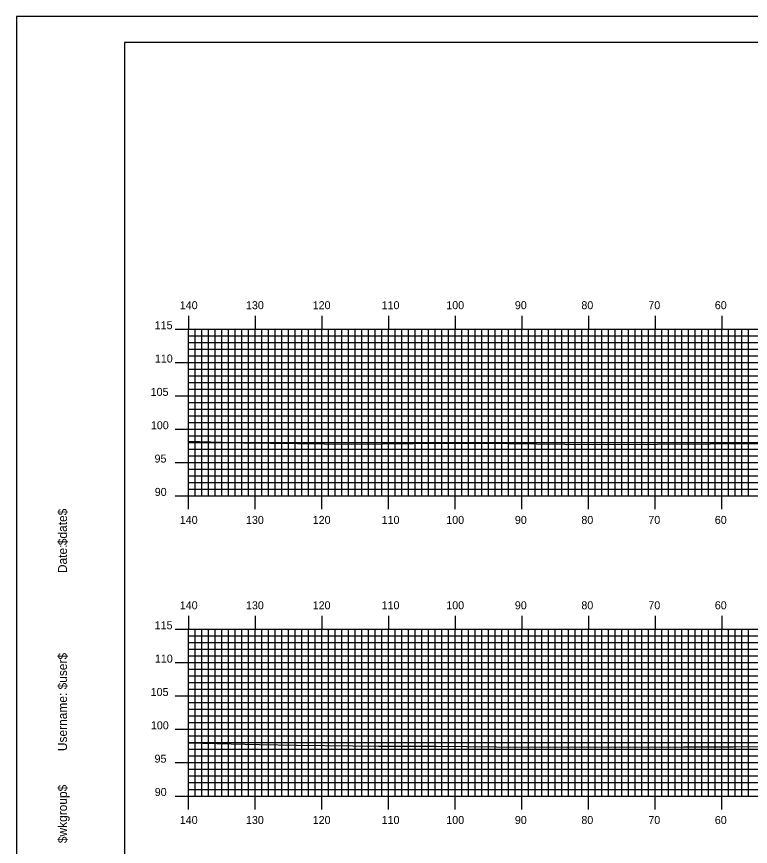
# Model space of a CAD drawing. Extents: x 1764939 to 1765282, y 442591 to 442811.
# Drawn here: x 1764939.1 to 1765049.2, y 442686.1 to 442810.5 of the extents above; entities that cross this region are included whole.
import ezdxf

# ---------------------------------------------------------------- set-up
doc = ezdxf.new("R2010")
doc.units = 0
for name, color, linetype in [('BORDER', 7, 'Continuous'), ('H_V ANNOTATION', 7, 'Continuous'), ('MAJOR', 7, 'Continuous'), ('MINOR', 7, 'Continuous'), ('PLOT BOUNDARY', 7, 'Continuous'), ('S_Roadway_Centerline', 7, 'Continuous')]:
    doc.layers.add(name, color=color, linetype=linetype)

msp = doc.modelspace()

# ---------------------------------------------------------------- linework, layer by layer
at = {"layer": 'BORDER'}
msp.add_lwpolyline([(1764955.26, 442596.67), (1765275.26, 442596.67), (1765275.26, 442806.67), (1764955.26, 442806.67)], close=True, dxfattribs=at)
at = {"layer": 'MAJOR'}
for p, q in [((1764964.86, 442765.67), (1764964.86, 442763.67)), ((1764974.86, 442765.67), (1764974.86, 442763.67)), ((1764984.86, 442765.67), (1764984.86, 442763.67)), ((1764994.86, 442765.67), (1764994.86, 442763.67)), ((1765004.86, 442765.67), (1765004.86, 442763.67)), ((1765014.86, 442765.67), (1765014.86, 442763.67)), ((1765024.86, 442765.67), (1765024.86, 442763.67)), ((1765034.86, 442765.67), (1765034.86, 442763.67)), ((1765044.86, 442765.67), (1765044.86, 442763.67)), ((1764962.85, 442763.67), (1764964.86, 442763.67)), ((1764964.86, 442763.67), (1765244.86, 442763.67)), ((1764964.86, 442738.67), (1764964.86, 442763.67)), ((1764964.86, 442738.67), (1764964.86, 442763.67)), ((1764964.86, 442763.67), (1765244.86, 442763.67)), ((1764974.86, 442738.67), (1764974.86, 442763.67)), ((1764984.86, 442738.67), (1764984.86, 442763.67)), ((1764994.86, 442738.67), (1764994.86, 442763.67)), ((1765004.86, 442738.67), (1765004.86, 442763.67)), ((1765014.86, 442738.67), (1765014.86, 442763.67)), ((1765024.86, 442738.67), (1765024.86, 442763.67)), ((1765034.86, 442738.67), (1765034.86, 442763.67)), ((1765044.86, 442738.67), (1765044.86, 442763.67)), ((1764962.85, 442758.67), (1764964.86, 442758.67)), ((1764964.86, 442758.67), (1765244.86, 442758.67)), ((1764962.85, 442753.67), (1764964.86, 442753.67)), ((1764964.86, 442753.67), (1765244.86, 442753.67)), ((1764962.85, 442748.67), (1764964.86, 442748.67)), ((1764964.86, 442748.67), (1765244.86, 442748.67)), ((1764962.85, 442743.67), (1764964.86, 442743.67)), ((1764964.86, 442743.67), (1765244.86, 442743.67)), ((1764962.85, 442738.67), (1764964.86, 442738.67)), ((1764964.86, 442738.67), (1765244.86, 442738.67)), ((1764964.86, 442738.67), (1765244.86, 442738.67)), ((1764964.86, 442736.66), (1764964.86, 442738.67)), ((1764974.86, 442736.66), (1764974.86, 442738.67)), ((1764984.86, 442736.66), (1764984.86, 442738.67)), ((1764994.86, 442736.66), (1764994.86, 442738.67)), ((1765004.86, 442736.66), (1765004.86, 442738.67)), ((1765014.86, 442736.66), (1765014.86, 442738.67)), ((1765024.86, 442736.66), (1765024.86, 442738.67)), ((1765034.86, 442736.66), (1765034.86, 442738.67)), ((1765044.86, 442736.66), (1765044.86, 442738.67)), ((1764964.86, 442720.67), (1764964.86, 442718.67)), ((1764974.86, 442720.67), (1764974.86, 442718.67)), ((1764984.86, 442720.67), (1764984.86, 442718.67)), ((1764994.86, 442720.67), (1764994.86, 442718.67)), ((1765004.86, 442720.67), (1765004.86, 442718.67)), ((1765014.86, 442720.67), (1765014.86, 442718.67)), ((1765024.86, 442720.67), (1765024.86, 442718.67)), ((1765034.86, 442720.67), (1765034.86, 442718.67)), ((1765044.86, 442720.67), (1765044.86, 442718.67)), ((1764962.85, 442718.67), (1764964.86, 442718.67)), ((1764964.86, 442718.67), (1765244.86, 442718.67)), ((1764964.86, 442693.67), (1764964.86, 442718.67)), ((1764964.86, 442693.67), (1764964.86, 442718.67)), ((1764964.86, 442718.67), (1765244.86, 442718.67)), ((1764974.86, 442693.67), (1764974.86, 442718.67)), ((1764984.86, 442693.67), (1764984.86, 442718.67)), ((1764994.86, 442693.67), (1764994.86, 442718.67)), ((1765004.86, 442693.67), (1765004.86, 442718.67)), ((1765014.86, 442693.67), (1765014.86, 442718.67)), ((1765024.86, 442693.67), (1765024.86, 442718.67)), ((1765034.86, 442693.67), (1765034.86, 442718.67)), ((1765044.86, 442693.67), (1765044.86, 442718.67)), ((1764962.85, 442713.67), (1764964.86, 442713.67)), ((1764964.86, 442713.67), (1765244.86, 442713.67)), ((1764962.85, 442708.67), (1764964.86, 442708.67)), ((1764964.86, 442708.67), (1765244.86, 442708.67)), ((1764962.85, 442703.67), (1764964.86, 442703.67)), ((1764964.86, 442703.67), (1765244.86, 442703.67)), ((1764962.85, 442698.67), (1764964.86, 442698.67)), ((1764964.86, 442698.67), (1765244.86, 442698.67)), ((1764962.85, 442693.67), (1764964.86, 442693.67)), ((1764964.86, 442693.67), (1765244.86, 442693.67)), ((1764964.86, 442693.67), (1765244.86, 442693.67)), ((1764964.86, 442691.66), (1764964.86, 442693.67)), ((1764974.86, 442691.66), (1764974.86, 442693.67)), ((1764984.86, 442691.66), (1764984.86, 442693.67)), ((1764994.86, 442691.66), (1764994.86, 442693.67)), ((1765004.86, 442691.66), (1765004.86, 442693.67)), ((1765014.86, 442691.66), (1765014.86, 442693.67)), ((1765024.86, 442691.66), (1765024.86, 442693.67)), ((1765034.86, 442691.66), (1765034.86, 442693.67)), ((1765044.86, 442691.66), (1765044.86, 442693.67))]:
    msp.add_line(p, q, dxfattribs=at)
at = {"layer": 'MINOR'}
for p, q in [((1764964.86, 442762.67), (1765244.86, 442762.67)), ((1764964.86, 442762.67), (1764966.86, 442762.67)), ((1764965.86, 442738.67), (1764965.86, 442763.67)), ((1764966.86, 442738.67), (1764966.86, 442763.67)), ((1764967.86, 442738.67), (1764967.86, 442763.67)), ((1764968.86, 442738.67), (1764968.86, 442763.67)), ((1764969.86, 442738.67), (1764969.86, 442763.67)), ((1764970.86, 442738.67), (1764970.86, 442763.67)), ((1764971.86, 442738.67), (1764971.86, 442763.67)), ((1764972.86, 442738.67), (1764972.86, 442763.67)), ((1764973.86, 442738.67), (1764973.86, 442763.67)), ((1764975.86, 442738.67), (1764975.86, 442763.67)), ((1764976.86, 442738.67), (1764976.86, 442763.67)), ((1764977.86, 442738.67), (1764977.86, 442763.67)), ((1764978.86, 442738.67), (1764978.86, 442763.67)), ((1764979.86, 442738.67), (1764979.86, 442763.67)), ((1764980.86, 442738.67), (1764980.86, 442763.67)), ((1764981.86, 442738.67), (1764981.86, 442763.67)), ((1764982.86, 442738.67), (1764982.86, 442763.67)), ((1764983.86, 442738.67), (1764983.86, 442763.67)), ((1764985.86, 442738.67), (1764985.86, 442763.67)), ((1764986.86, 442738.67), (1764986.86, 442763.67)), ((1764987.86, 442738.67), (1764987.86, 442763.67)), ((1764988.86, 442738.67), (1764988.86, 442763.67)), ((1764989.86, 442738.67), (1764989.86, 442763.67)), ((1764990.86, 442738.67), (1764990.86, 442763.67)), ((1764991.86, 442738.67), (1764991.86, 442763.67)), ((1764992.86, 442738.67), (1764992.86, 442763.67)), ((1764993.86, 442738.67), (1764993.86, 442763.67)), ((1764995.86, 442738.67), (1764995.86, 442763.67)), ((1764996.86, 442738.67), (1764996.86, 442763.67)), ((1764997.86, 442738.67), (1764997.86, 442763.67)), ((1764998.86, 442738.67), (1764998.86, 442763.67)), ((1764999.86, 442738.67), (1764999.86, 442763.67)), ((1765000.86, 442738.67), (1765000.86, 442763.67)), ((1765001.86, 442738.67), (1765001.86, 442763.67)), ((1765002.86, 442738.67), (1765002.86, 442763.67)), ((1765003.86, 442738.67), (1765003.86, 442763.67)), ((1765005.86, 442738.67), (1765005.86, 442763.67)), ((1765006.86, 442738.67), (1765006.86, 442763.67)), ((1765007.86, 442738.67), (1765007.86, 442763.67)), ((1765008.86, 442738.67), (1765008.86, 442763.67)), ((1765009.86, 442738.67), (1765009.86, 442763.67)), ((1765010.86, 442738.67), (1765010.86, 442763.67)), ((1765011.86, 442738.67), (1765011.86, 442763.67)), ((1765012.86, 442738.67), (1765012.86, 442763.67)), ((1765013.86, 442738.67), (1765013.86, 442763.67)), ((1765015.86, 442738.67), (1765015.86, 442763.67)), ((1765016.86, 442738.67), (1765016.86, 442763.67)), ((1765017.86, 442738.67), (1765017.86, 442763.67)), ((1765018.86, 442738.67), (1765018.86, 442763.67)), ((1765019.86, 442738.67), (1765019.86, 442763.67)), ((1765020.86, 442738.67), (1765020.86, 442763.67)), ((1765021.86, 442738.67), (1765021.86, 442763.67)), ((1765022.86, 442738.67), (1765022.86, 442763.67)), ((1765023.86, 442738.67), (1765023.86, 442763.67)), ((1765025.86, 442738.67), (1765025.86, 442763.67)), ((1765026.86, 442738.67), (1765026.86, 442763.67)), ((1765027.86, 442738.67), (1765027.86, 442763.67)), ((1765028.86, 442738.67), (1765028.86, 442763.67)), ((1765029.86, 442738.67), (1765029.86, 442763.67)), ((1765030.86, 442738.67), (1765030.86, 442763.67)), ((1765031.86, 442738.67), (1765031.86, 442763.67)), ((1765032.86, 442738.67), (1765032.86, 442763.67)), ((1765033.86, 442738.67), (1765033.86, 442763.67)), ((1765035.86, 442738.67), (1765035.86, 442763.67)), ((1765036.86, 442738.67), (1765036.86, 442763.67)), ((1765037.86, 442738.67), (1765037.86, 442763.67)), ((1765038.86, 442738.67), (1765038.86, 442763.67)), ((1765039.86, 442738.67), (1765039.86, 442763.67)), ((1765040.86, 442738.67), (1765040.86, 442763.67)), ((1765041.86, 442738.67), (1765041.86, 442763.67)), ((1765042.86, 442738.67), (1765042.86, 442763.67)), ((1765043.86, 442738.67), (1765043.86, 442763.67)), ((1765045.86, 442738.67), (1765045.86, 442763.67)), ((1765046.86, 442738.67), (1765046.86, 442763.67)), ((1765047.86, 442738.67), (1765047.86, 442763.67)), ((1765048.86, 442738.67), (1765048.86, 442763.67)), ((1764964.86, 442761.67), (1765244.86, 442761.67)), ((1764964.86, 442761.67), (1764966.86, 442761.67)), ((1764964.86, 442760.67), (1765244.86, 442760.67)), ((1764964.86, 442760.67), (1764966.86, 442760.67)), ((1764964.86, 442759.67), (1765244.86, 442759.67)), ((1764964.86, 442759.67), (1764966.86, 442759.67)), ((1764964.86, 442757.67), (1765244.86, 442757.67)), ((1764964.86, 442757.67), (1764966.86, 442757.67)), ((1764964.86, 442756.67), (1765244.86, 442756.67)), ((1764964.86, 442756.67), (1764966.86, 442756.67)), ((1764964.86, 442755.67), (1765244.86, 442755.67)), ((1764964.86, 442755.67), (1764966.86, 442755.67)), ((1764964.86, 442754.67), (1765244.86, 442754.67)), ((1764964.86, 442754.67), (1764966.86, 442754.67)), ((1764964.86, 442752.67), (1765244.86, 442752.67)), ((1764964.86, 442752.67), (1764966.86, 442752.67)), ((1764964.86, 442751.67), (1765244.86, 442751.67)), ((1764964.86, 442751.67), (1764966.86, 442751.67)), ((1764964.86, 442750.67), (1765244.86, 442750.67)), ((1764964.86, 442750.67), (1764966.86, 442750.67)), ((1764964.86, 442749.67), (1765244.86, 442749.67)), ((1764964.86, 442749.67), (1764966.86, 442749.67)), ((1764964.86, 442747.67), (1765244.86, 442747.67)), ((1764964.86, 442747.67), (1764966.86, 442747.67)), ((1764964.86, 442746.67), (1765244.86, 442746.67)), ((1764964.86, 442746.67), (1764966.86, 442746.67)), ((1764964.86, 442745.67), (1765244.86, 442745.67)), ((1764964.86, 442745.67), (1764966.86, 442745.67)), ((1764964.86, 442744.67), (1765244.86, 442744.67)), ((1764964.86, 442744.67), (1764966.86, 442744.67)), ((1764964.86, 442742.67), (1765244.86, 442742.67)), ((1764964.86, 442742.67), (1764966.86, 442742.67)), ((1764964.86, 442741.67), (1765244.86, 442741.67)), ((1764964.86, 442741.67), (1764966.86, 442741.67)), ((1764964.86, 442740.67), (1765244.86, 442740.67)), ((1764964.86, 442740.67), (1764966.86, 442740.67)), ((1764964.86, 442739.67), (1765244.86, 442739.67)), ((1764964.86, 442739.67), (1764966.86, 442739.67)), ((1764965.86, 442693.67), (1764965.86, 442718.67)), ((1764966.86, 442693.67), (1764966.86, 442718.67)), ((1764967.86, 442693.67), (1764967.86, 442718.67)), ((1764968.86, 442693.67), (1764968.86, 442718.67)), ((1764969.86, 442693.67), (1764969.86, 442718.67)), ((1764970.86, 442693.67), (1764970.86, 442718.67)), ((1764971.86, 442693.67), (1764971.86, 442718.67)), ((1764972.86, 442693.67), (1764972.86, 442718.67)), ((1764973.86, 442693.67), (1764973.86, 442718.67)), ((1764975.86, 442693.67), (1764975.86, 442718.67)), ((1764976.86, 442693.67), (1764976.86, 442718.67)), ((1764977.86, 442693.67), (1764977.86, 442718.67)), ((1764978.86, 442693.67), (1764978.86, 442718.67)), ((1764979.86, 442693.67), (1764979.86, 442718.67)), ((1764980.86, 442693.67), (1764980.86, 442718.67)), ((1764981.86, 442693.67), (1764981.86, 442718.67)), ((1764982.86, 442693.67), (1764982.86, 442718.67)), ((1764983.86, 442693.67), (1764983.86, 442718.67)), ((1764985.86, 442693.67), (1764985.86, 442718.67)), ((1764986.86, 442693.67), (1764986.86, 442718.67)), ((1764987.86, 442693.67), (1764987.86, 442718.67)), ((1764988.86, 442693.67), (1764988.86, 442718.67)), ((1764989.86, 442693.67), (1764989.86, 442718.67)), ((1764990.86, 442693.67), (1764990.86, 442718.67)), ((1764991.86, 442693.67), (1764991.86, 442718.67)), ((1764992.86, 442693.67), (1764992.86, 442718.67)), ((1764993.86, 442693.67), (1764993.86, 442718.67)), ((1764995.86, 442693.67), (1764995.86, 442718.67)), ((1764996.86, 442693.67), (1764996.86, 442718.67)), ((1764997.86, 442693.67), (1764997.86, 442718.67)), ((1764998.86, 442693.67), (1764998.86, 442718.67)), ((1764999.86, 442693.67), (1764999.86, 442718.67)), ((1765000.86, 442693.67), (1765000.86, 442718.67)), ((1765001.86, 442693.67), (1765001.86, 442718.67)), ((1765002.86, 442693.67), (1765002.86, 442718.67)), ((1765003.86, 442693.67), (1765003.86, 442718.67)), ((1765005.86, 442693.67), (1765005.86, 442718.67)), ((1765006.86, 442693.67), (1765006.86, 442718.67)), ((1765007.86, 442693.67), (1765007.86, 442718.67)), ((1765008.86, 442693.67), (1765008.86, 442718.67)), ((1765009.86, 442693.67), (1765009.86, 442718.67)), ((1765010.86, 442693.67), (1765010.86, 442718.67)), ((1765011.86, 442693.67), (1765011.86, 442718.67)), ((1765012.86, 442693.67), (1765012.86, 442718.67)), ((1765013.86, 442693.67), (1765013.86, 442718.67)), ((1765015.86, 442693.67), (1765015.86, 442718.67)), ((1765016.86, 442693.67), (1765016.86, 442718.67)), ((1765017.86, 442693.67), (1765017.86, 442718.67)), ((1765018.86, 442693.67), (1765018.86, 442718.67)), ((1765019.86, 442693.67), (1765019.86, 442718.67)), ((1765020.86, 442693.67), (1765020.86, 442718.67)), ((1765021.86, 442693.67), (1765021.86, 442718.67)), ((1765022.86, 442693.67), (1765022.86, 442718.67)), ((1765023.86, 442693.67), (1765023.86, 442718.67)), ((1765025.86, 442693.67), (1765025.86, 442718.67)), ((1765026.86, 442693.67), (1765026.86, 442718.67)), ((1765027.86, 442693.67), (1765027.86, 442718.67)), ((1765028.86, 442693.67), (1765028.86, 442718.67)), ((1765029.86, 442693.67), (1765029.86, 442718.67)), ((1765030.86, 442693.67), (1765030.86, 442718.67)), ((1765031.86, 442693.67), (1765031.86, 442718.67)), ((1765032.86, 442693.67), (1765032.86, 442718.67)), ((1765033.86, 442693.67), (1765033.86, 442718.67)), ((1765035.86, 442693.67), (1765035.86, 442718.67)), ((1765036.86, 442693.67), (1765036.86, 442718.67)), ((1765037.86, 442693.67), (1765037.86, 442718.67)), ((1765038.86, 442693.67), (1765038.86, 442718.67)), ((1765039.86, 442693.67), (1765039.86, 442718.67)), ((1765040.86, 442693.67), (1765040.86, 442718.67)), ((1765041.86, 442693.67), (1765041.86, 442718.67)), ((1765042.86, 442693.67), (1765042.86, 442718.67)), ((1765043.86, 442693.67), (1765043.86, 442718.67)), ((1765045.86, 442693.67), (1765045.86, 442718.67)), ((1765046.86, 442693.67), (1765046.86, 442718.67)), ((1765047.86, 442693.67), (1765047.86, 442718.67)), ((1765048.86, 442693.67), (1765048.86, 442718.67)), ((1764964.86, 442717.67), (1765244.86, 442717.67)), ((1764964.86, 442717.67), (1764966.86, 442717.67)), ((1764964.86, 442716.67), (1765244.86, 442716.67)), ((1764964.86, 442716.67), (1764966.86, 442716.67)), ((1764964.86, 442715.67), (1765244.86, 442715.67)), ((1764964.86, 442715.67), (1764966.86, 442715.67)), ((1764964.86, 442714.67), (1765244.86, 442714.67)), ((1764964.86, 442714.67), (1764966.86, 442714.67)), ((1764964.86, 442712.67), (1765244.86, 442712.67)), ((1764964.86, 442712.67), (1764966.86, 442712.67)), ((1764964.86, 442711.67), (1765244.86, 442711.67)), ((1764964.86, 442711.67), (1764966.86, 442711.67)), ((1764964.86, 442710.67), (1765244.86, 442710.67)), ((1764964.86, 442710.67), (1764966.86, 442710.67)), ((1764964.86, 442709.67), (1765244.86, 442709.67)), ((1764964.86, 442709.67), (1764966.86, 442709.67)), ((1764964.86, 442707.67), (1765244.86, 442707.67)), ((1764964.86, 442707.67), (1764966.86, 442707.67)), ((1764964.86, 442706.67), (1765244.86, 442706.67)), ((1764964.86, 442706.67), (1764966.86, 442706.67)), ((1764964.86, 442705.67), (1765244.86, 442705.67)), ((1764964.86, 442705.67), (1764966.86, 442705.67)), ((1764964.86, 442704.67), (1765244.86, 442704.67)), ((1764964.86, 442704.67), (1764966.86, 442704.67)), ((1764964.86, 442702.67), (1765244.86, 442702.67)), ((1764964.86, 442702.67), (1764966.86, 442702.67)), ((1764964.86, 442701.67), (1765244.86, 442701.67)), ((1764964.86, 442701.67), (1764966.86, 442701.67)), ((1764964.86, 442700.67), (1765244.86, 442700.67)), ((1764964.86, 442700.67), (1764966.86, 442700.67)), ((1764964.86, 442699.67), (1765244.86, 442699.67)), ((1764964.86, 442699.67), (1764966.86, 442699.67)), ((1764964.86, 442697.67), (1765244.86, 442697.67)), ((1764964.86, 442697.67), (1764966.86, 442697.67)), ((1764964.86, 442696.67), (1765244.86, 442696.67)), ((1764964.86, 442696.67), (1764966.86, 442696.67)), ((1764964.86, 442695.67), (1765244.86, 442695.67)), ((1764964.86, 442695.67), (1764966.86, 442695.67)), ((1764964.86, 442694.67), (1765244.86, 442694.67)), ((1764964.86, 442694.67), (1764966.86, 442694.67))]:
    msp.add_line(p, q, dxfattribs=at)
at = {"layer": 'PLOT BOUNDARY'}
msp.add_lwpolyline([(1764939.07, 442590.55), (1765279.07, 442590.55), (1765279.07, 442810.55), (1764939.07, 442810.55)], close=True, dxfattribs=at)
at = {"layer": 'S_Roadway_Centerline'}
for points in [[(1764964.86, 442746.9), (1764971.57, 442746.67), (1764973.13, 442746.64), (1764989.31, 442746.45), (1765003.23, 442746.56), (1765007.52, 442746.58), (1765009.15, 442746.58), (1765012.9, 442746.53), (1765025.55, 442746.38), (1765035.19, 442746.45), (1765043.15, 442746.5), (1765053.94, 442746.55)], [(1764964.86, 442701.63), (1764975.54, 442701.37), (1764981.07, 442701.29), (1764989.53, 442701.2), (1764993.37, 442701.15), (1765002.05, 442701.13), (1765011.09, 442701.06), (1765021.71, 442701.01), (1765024.34, 442701.03), (1765028.97, 442700.98), (1765039.14, 442701.02), (1765046.64, 442701.06), (1765062.57, 442701.25)]]:
    msp.add_lwpolyline(points, dxfattribs=at)

# ---------------------------------------------------------------- texts
at = {"layer": 'BORDER'}
for s, p in [('$date$', (1764946.63, 442731.28)), ('Date:', (1764946.63, 442727.1)), ('$user$', (1764946.63, 442709.65)), ('Username:', (1764946.63, 442700.4)), ('$wkgroup$', (1764946.63, 442686.6))]:
    msp.add_text(s, height=1.339, rotation=90, dxfattribs=at).set_placement(p)
at = {"layer": 'H_V ANNOTATION'}
for s, p in [('140', (1764963.56, 442766.67)), ('130', (1764973.49, 442766.67)), ('120', (1764983.5, 442766.67)), ('110', (1764993.84, 442766.67)), ('100', (1765003.54, 442766.67)), ('90', (1765013.83, 442766.67)), ('80', (1765023.81, 442766.67)), ('70', (1765033.86, 442766.67)), ('60', (1765043.83, 442766.67)), ('115', (1764959.79, 442763.67)), ('110', (1764959.82, 442758.67)), ('105', (1764959.19, 442753.67)), ('100', (1764959.22, 442748.67)), ('95', (1764959.77, 442743.67)), ('90', (1764959.8, 442738.67)), ('140', (1764963.56, 442734.47)), ('130', (1764973.49, 442734.47)), ('120', (1764983.5, 442734.47)), ('110', (1764993.84, 442734.47)), ('100', (1765003.54, 442734.47)), ('90', (1765013.83, 442734.47)), ('80', (1765023.81, 442734.47)), ('70', (1765033.86, 442734.47)), ('60', (1765043.83, 442734.47)), ('140', (1764963.56, 442721.67)), ('130', (1764973.49, 442721.67)), ('120', (1764983.5, 442721.67)), ('110', (1764993.84, 442721.67)), ('100', (1765003.54, 442721.67)), ('90', (1765013.83, 442721.67)), ('80', (1765023.81, 442721.67)), ('70', (1765033.86, 442721.67)), ('60', (1765043.83, 442721.67)), ('115', (1764959.79, 442718.67)), ('110', (1764959.82, 442713.67)), ('105', (1764959.19, 442708.67)), ('100', (1764959.22, 442703.67)), ('95', (1764959.77, 442698.67)), ('90', (1764959.8, 442693.67)), ('140', (1764963.56, 442689.47)), ('130', (1764973.49, 442689.47)), ('120', (1764983.5, 442689.47)), ('110', (1764993.84, 442689.47)), ('100', (1765003.54, 442689.47)), ('90', (1765013.83, 442689.47)), ('80', (1765023.81, 442689.47)), ('70', (1765033.86, 442689.47)), ('60', (1765043.83, 442689.47))]:
    msp.add_text(s, height=1.2, dxfattribs=at).set_placement(p)
at = {"layer": 'MAJOR'}
for p in [(1764964.85, 442738.67), (1764964.85, 442693.67)]:
    msp.add_text('-', height=0.012, dxfattribs=at).set_placement(p)

doc.saveas('drawing.dxf')
